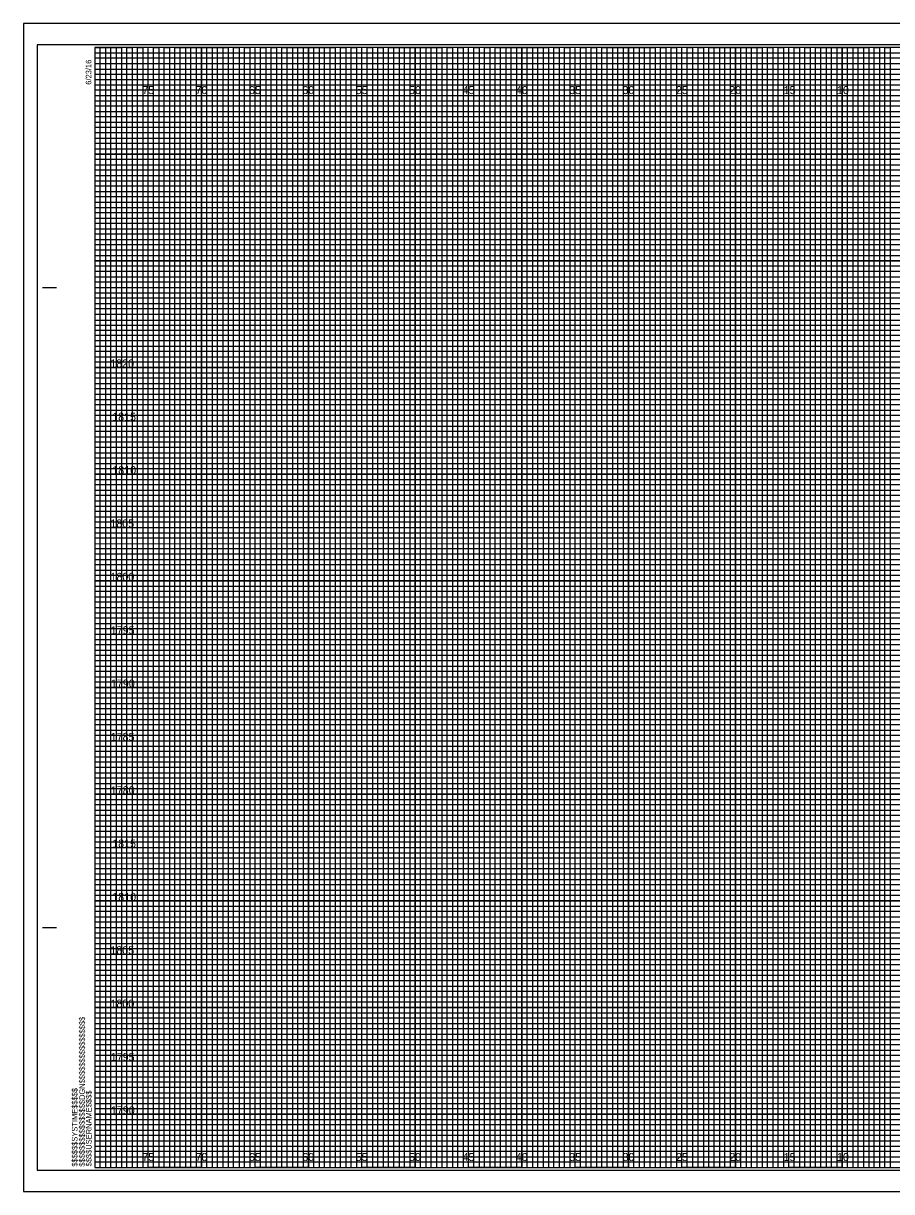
# Model space of a CAD drawing. Extents: x -7 to 162, y -2 to 767.
# Drawn here: x -6.7 to 74.6, y 327.7 to 437.2 of the extents above; entities that cross this region are included whole.
import ezdxf

# ---------------------------------------------------------------- set-up
doc = ezdxf.new("R2010")
doc.units = 0
for name, color, linetype in [('Prop Grid Mask', 7, 'Continuous'), ('Prop XS Elevation Labels', 7, 'Continuous'), ('Sheet Cross Section CELL', 7, 'Continuous'), ('Sheet Cross Section Grid Major CELL', 7, 'Continuous'), ('Sheet Cross Section Grid Middle CELL', 7, 'Continuous'), ('Sheet Cross Section Grid Minor 1 CELL', 7, 'Continuous'), ('Sheet Cross Section Grid Minor 2 CELL', 7, 'Continuous'), ('Sheet Cutting Line CELL', 7, 'Continuous'), ('Sheet DOT Grid CELL', 7, 'Continuous'), ('Sheet Plot Border Inside CELL', 7, 'Continuous'), ('Sheet Plot Border Outside CELL', 7, 'Continuous')]:
    doc.layers.add(name, color=color, linetype=linetype)

msp = doc.modelspace()

# ---------------------------------------------------------------- linework, layer by layer
at = {"layer": 'Sheet Cross Section CELL'}
for p, q in [((-4.9, 412.5), (-3.65, 412.5)), ((-4.85, 412.5), (-3.6, 412.5)), ((-4.9, 352.5), (-3.65, 352.5)), ((-4.85, 352.5), (-3.6, 352.5)), ((0, 330), (0, 330)), ((0, 330), (0, 330)), ((0, 330), (0, 330)), ((0, 330), (0, 330)), ((0, 330), (0, 330)), ((0, 330), (0, 330)), ((0, 330), (0, 330))]:
    msp.add_line(p, q, dxfattribs=at)
msp.add_lwpolyline([(160, 435), (0, 435), (0, 330), (160, 330)], close=True, dxfattribs=at)
at = {"layer": 'Sheet Cross Section Grid Major CELL'}
for p, q in [((5, 435), (0, 435)), ((5, 330), (5, 435)), ((15, 435), (10, 435)), ((10, 435), (10, 330)), ((15, 330), (15, 435)), ((25, 435), (20, 435)), ((20, 435), (20, 330)), ((25, 330), (25, 435)), ((35, 435), (30, 435)), ((30, 435), (30, 330)), ((35, 330), (35, 435)), ((45, 435), (40, 435)), ((40, 435), (40, 330)), ((45, 330), (45, 435)), ((55, 435), (50, 435)), ((50, 435), (50, 330)), ((55, 330), (55, 435)), ((65, 435), (60, 435)), ((60, 435), (60, 330)), ((65, 330), (65, 435)), ((75, 435), (70, 435)), ((70, 435), (70, 330)), ((10, 330), (5, 330)), ((20, 330), (15, 330)), ((30, 330), (25, 330)), ((40, 330), (35, 330)), ((50, 330), (45, 330)), ((60, 330), (55, 330)), ((70, 330), (65, 330))]:
    msp.add_line(p, q, dxfattribs=at)
for points in [[(0, 430), (160, 430), (160, 425), (0, 425)], [(0, 420), (160, 420), (160, 415), (0, 415)], [(0, 410), (160, 410), (160, 405), (0, 405)], [(0, 400), (160, 400), (160, 395), (0, 395)], [(0, 390), (160, 390), (160, 385), (0, 385)], [(0, 380), (160, 380), (160, 375), (0, 375)], [(0, 370), (160, 370), (160, 365), (0, 365)], [(0, 360), (160, 360), (160, 355), (0, 355)], [(0, 350), (160, 350), (160, 345), (0, 345)], [(0, 340), (160, 340), (160, 335), (0, 335)]]:
    msp.add_lwpolyline(points, dxfattribs=at)
at = {"layer": 'Sheet Cross Section Grid Middle CELL'}
for points in [[(0, 435), (2.5, 435), (2.5, 330), (7.5, 330), (7.5, 435), (12.5, 435), (12.5, 330), (17.5, 330), (17.5, 435), (22.5, 435), (22.5, 330), (27.5, 330), (27.5, 435), (32.5, 435), (32.5, 330), (37.5, 330), (37.5, 435), (42.5, 435), (42.5, 330), (47.5, 330), (47.5, 435), (52.5, 435), (52.5, 330), (57.5, 330), (57.5, 435), (62.5, 435), (62.5, 330), (67.5, 330), (67.5, 435), (72.5, 435), (72.5, 330), (77.5, 330)], [(0, 432.5), (137.5, 432.5)], [(0, 422.5), (160, 422.5), (160, 427.5), (0, 427.5)], [(0, 412.5), (160, 412.5), (160, 417.5), (0, 417.5)], [(0, 402.5), (160, 402.5), (160, 407.5), (0, 407.5)], [(0, 392.5), (160, 392.5), (160, 397.5), (0, 397.5)], [(0, 382.5), (160, 382.5), (160, 387.5), (0, 387.5)], [(0, 372.5), (160, 372.5), (160, 377.5), (0, 377.5)], [(0, 362.5), (160, 362.5), (160, 367.5), (0, 367.5)], [(0, 352.5), (160, 352.5), (160, 357.5), (0, 357.5)], [(0, 342.5), (160, 342.5), (160, 347.5), (0, 347.5)], [(0, 332.5), (160, 332.5), (160, 337.5), (0, 337.5)]]:
    msp.add_lwpolyline(points, dxfattribs=at)
at = {"layer": 'Sheet Cross Section Grid Minor 1 CELL'}
for p, q in [((0, 434.5), (130, 434.5)), ((130, 433.99), (0, 433.99)), ((0, 433.99), (0, 433.5)), ((0, 433.5), (130, 433.5)), ((130, 432.94), (0, 432.94)), ((0, 432.94), (0, 432)), ((0, 432), (160, 432))]:
    msp.add_line(p, q, dxfattribs=at)
for points in [[(0, 431.5), (135, 431.5), (160, 431.5), (160, 431), (0, 431)], [(0, 430.5), (160, 430.5), (160, 429.5), (0, 429.5)], [(0, 429), (160, 429), (160, 428.5), (0, 428.49)], [(0, 428), (160, 428), (160, 427), (0, 427)], [(0, 426.5), (160, 426.5), (160, 426), (0, 426)], [(0, 425.5), (160, 425.5), (160, 424.5), (0, 424.5)], [(0, 424), (160, 424), (160, 423.5), (0, 423.5)], [(0, 423), (160, 423), (160, 422), (0, 422)], [(0, 421.5), (160, 421.5), (160, 421), (0, 421)], [(0, 420.5), (160, 420.5), (160, 419.5), (0, 419.5)], [(0, 419), (160, 419), (160, 418.5), (0, 418.5)], [(0, 418), (160, 418), (160, 416.98), (160, 416.5), (160, 416), (0, 416)], [(0, 417), (160, 417), (160, 416.5), (0, 416.5)], [(0, 415.5), (160, 415.5), (160, 414.5), (0, 414.51)], [(0, 414.51), (160, 414.5), (160, 414), (0, 414)], [(0, 413.5), (160, 413.5), (160, 413), (0, 413)], [(0, 412), (160, 412), (160, 411.5), (0, 411.5)], [(0, 411), (160, 411), (160, 410.5), (0, 410.5)], [(-0.04, 409.44), (160, 409.44), (160, 408.94), (-0.04, 408.94)], [(0, 408.5), (160, 408.5), (160, 408), (0, 408)], [(0, 407), (160, 407), (160, 406.5), (0, 406.5)], [(0, 406), (160, 406), (160, 405.5), (0, 405.5)], [(0, 404.5), (160, 404.5), (160, 404), (0, 404)], [(0, 403.5), (160, 403.5), (160, 403), (0, 403)], [(0, 402), (160, 402), (160, 401.5), (0, 401.5)], [(0, 401), (160, 401), (160, 400.5), (0, 400.5)], [(0, 399.5), (160, 399.5), (160, 398.99), (0, 399)], [(0, 398.5), (160, 398.5), (160, 398), (0, 398)], [(0, 397), (160, 397), (160, 396.5), (0, 396.5)], [(0, 396), (160, 396), (160, 395.5), (0, 395.5)], [(0, 394.5), (160, 394.5), (160, 394), (0, 394)], [(0, 393.5), (160, 393.5), (160, 393), (0, 393)], [(0, 392), (160, 392), (160, 391.5), (0, 391.5)], [(0, 391), (160, 391), (160, 390.5), (0, 390.5)], [(0, 389.5), (160, 389.5), (160, 389), (0, 389)], [(0, 388.5), (160.03, 388.45), (160, 388), (0, 388)], [(0, 387), (160, 387), (160, 386.5), (0, 386.5)], [(0, 386), (160, 386), (160, 385.5), (0, 385.5)], [(0, 384.5), (160, 384.5), (160, 384), (0, 384)], [(0, 383.5), (160, 383.5), (160, 383), (0, 383)], [(0, 382), (160, 382), (160, 381.5), (0, 381.5)], [(0, 381), (160, 381), (160, 380.5), (0, 380.5)], [(0, 379.5), (160, 379.5), (160, 379), (0, 379)], [(0, 378.5), (160, 378.5), (160, 378), (0, 378)], [(0, 377), (160, 377), (160, 376.5), (0, 376.5)], [(0, 376), (160, 376), (160, 375.5), (0, 375.5)], [(0, 374.5), (160, 374.5), (160, 374), (0, 374)], [(0, 373.5), (160, 373.5), (160, 373), (0, 373)], [(0, 372), (160, 372), (160, 371.5), (0, 371.5)], [(0, 371), (160, 371), (160, 370.5), (0, 370.5)], [(0, 369.5), (160, 369.5), (160, 368.99), (0, 369)], [(0, 368.5), (160, 368.5), (160, 368), (0, 368)], [(0, 367), (160, 367), (160, 366.5), (0, 366.5)], [(0, 366), (160, 366), (160, 365.5), (0, 365.5)], [(0, 364.5), (160, 364.5), (160, 364), (0, 364)], [(0, 363.5), (160, 363.5), (160, 363), (0, 363)], [(0, 362), (160, 362), (160, 361.5), (0, 361.5)], [(0, 361), (160, 361), (160, 360.5), (0, 360.5)], [(0, 359.5), (160, 359.5), (160, 359), (0, 359)], [(0, 358.5), (160.03, 358.45), (160, 358), (0, 358)], [(0, 357), (160, 357), (160, 356.5), (0, 356.5)], [(0, 356), (160, 356), (160, 355.5), (0, 355.5)], [(0, 354.5), (160, 354.5), (160, 354), (0, 354)], [(0, 353.5), (160, 353.5), (160, 353), (0, 353)], [(0, 352), (160, 352), (160, 351.5), (0, 351.5)], [(0, 351), (160, 351), (160, 350.5), (0, 350.5)], [(0, 349.5), (160, 349.5), (160, 349), (0, 349)], [(0, 348.5), (160, 348.5), (160, 348), (0, 348)], [(0, 347), (160, 347), (160, 346.5), (0, 346.5)], [(0, 346), (160, 346), (160, 345.5), (0, 345.5)], [(0, 344.5), (160, 344.5), (160, 344), (0, 344)], [(0, 343.5), (160, 343.5), (160, 343), (0, 343)], [(0, 342), (160, 342), (160, 341.5), (0, 341.5)], [(0, 341), (160, 341), (160, 340.5), (0, 340.5)], [(0, 339.5), (160, 339.5), (160, 339), (0, 339)], [(0, 338.5), (160, 338.5), (160, 338), (0, 338)], [(0, 337), (160, 337), (160, 336.5), (0, 336.5)], [(0, 336), (160, 336), (160, 335.5), (0, 335.5)], [(0, 334.5), (160, 334.5), (160, 334), (0, 334)], [(0, 333.5), (160, 333.5), (160, 333), (0, 333)], [(0, 332), (160, 332), (160, 331.5), (0, 331.5)], [(0, 331), (160, 331), (160, 330.5), (0, 330.5)]]:
    msp.add_lwpolyline(points, dxfattribs=at)
at = {"layer": 'Sheet Cross Section Grid Minor 2 CELL'}
for points in [[(0, 330), (0.5, 330), (0.5, 435), (1, 435), (1, 330)], [(1, 330), (1.5, 330), (1.5, 435), (2, 435), (2, 330)], [(2.5, 330), (3, 330), (3, 435), (3.5, 435), (3.5, 330)], [(3.5, 330), (4, 330), (4, 435), (4.5, 435), (4.5, 330)], [(5, 330), (5.5, 330), (5.5, 435), (6, 435), (6, 330)], [(6, 330), (6.5, 330), (6.5, 435), (7, 435), (7, 330)], [(7.5, 330), (8, 330), (8, 435), (8.5, 435), (8.5, 330)], [(8.5, 330), (9, 330), (9, 435), (9.5, 435), (9.5, 330)], [(10, 330), (10.5, 330), (10.5, 435), (11, 435), (11, 330)], [(11, 330), (11.5, 330), (11.5, 435), (12, 435), (12, 330)], [(12.5, 330), (13, 330), (13, 435), (13.5, 435), (13.5, 330)], [(13.5, 330), (14, 330), (14, 435), (14.5, 435), (14.5, 330)], [(15, 330), (15.5, 330), (15.5, 435), (16, 435), (16, 330)], [(16, 330), (16.5, 330), (16.5, 435), (17, 435), (17, 330)], [(17.5, 330), (18, 330), (18, 435), (18.5, 435), (18.5, 330)], [(18.5, 330), (19, 330), (19, 435), (19.5, 435), (19.5, 330)], [(20, 330), (20.5, 330), (20.5, 435), (21, 435), (21, 330)], [(21, 330), (21.5, 330), (21.5, 435), (22, 435), (22, 330)], [(22.5, 330), (23, 330), (23, 435), (23.5, 435), (23.5, 330)], [(23.5, 330), (24, 330), (24, 435), (24.5, 435), (24.5, 330)], [(25, 330), (25.5, 330), (25.5, 435), (26, 435), (26, 330)], [(26, 330), (26.5, 330), (26.5, 435), (27, 435), (27, 330)], [(27.5, 330), (28, 330), (28, 435), (28.5, 435), (28.5, 330)], [(28.5, 330), (29, 330), (29, 435), (29.5, 435), (29.5, 330)], [(30, 330), (30.5, 330), (30.5, 435), (31, 435), (31, 330)], [(31, 330), (31.5, 330), (31.5, 435), (32, 435), (32, 330)], [(32.5, 330), (33, 330), (33, 435), (33.5, 435), (33.5, 330)], [(33.5, 330), (34, 330), (34, 435), (34.5, 435), (34.5, 330)], [(35, 330), (35.5, 330), (35.5, 435), (36, 435), (36, 330)], [(36, 330), (36.5, 330), (36.5, 435), (37, 435), (37, 330)], [(37.5, 330), (38, 330), (38, 435), (38.5, 435), (38.5, 330)], [(38.5, 330), (39, 330), (39, 435), (39.5, 435), (39.5, 330)], [(40, 330), (40.5, 330), (40.5, 435), (41, 435), (41, 330)], [(41, 330), (41.5, 330), (41.5, 435), (42, 435), (42, 330)], [(42.5, 330), (43, 330), (43, 435), (43.5, 435), (43.5, 330)], [(43.5, 330), (44, 330), (44, 435), (44.5, 435), (44.5, 330)], [(45, 330), (45.5, 330), (45.5, 435), (46, 435), (46, 330)], [(46, 330), (46.5, 330), (46.5, 435), (47, 435), (47, 330)], [(47.5, 330), (48, 330), (48, 435), (48.5, 435), (48.5, 330)], [(48.5, 330), (49, 330), (49, 435), (49.5, 435), (49.5, 330)], [(50, 330), (50.5, 330), (50.5, 435), (51, 435), (51, 330)], [(51, 330), (51.5, 330), (51.5, 435), (52, 435), (52, 330)], [(52.5, 330), (53, 330), (53, 435), (53.5, 435), (53.5, 330)], [(53.5, 330), (54, 330), (54, 435), (54.5, 435), (54.5, 330)], [(55, 330), (55.5, 330), (55.5, 435), (56, 435), (56, 330)], [(56, 330), (56.5, 330), (56.5, 435), (57, 435), (57, 330)], [(57.5, 330), (58, 330), (58, 435), (58.5, 435), (58.5, 330)], [(58.5, 330), (59, 330), (59, 435), (59.5, 435), (59.5, 330)], [(60, 330), (60.5, 330), (60.5, 435), (61, 435), (61, 330)], [(61, 330), (61.5, 330), (61.5, 435), (62, 435), (62, 330)], [(62.5, 330), (63, 330), (63, 435), (63.5, 435), (63.5, 330)], [(63.5, 330), (64, 330), (64, 435), (64.5, 435), (64.5, 330)], [(65, 330), (65.5, 330), (65.5, 435), (66, 435), (66, 330)], [(66, 330), (66.5, 330), (66.5, 435), (67, 435), (67, 330)], [(67.5, 330), (68, 330), (68, 435), (68.5, 435), (68.5, 330)], [(68.5, 330), (69, 330), (69, 435), (69.5, 435), (69.5, 330)], [(70, 330), (70.5, 330), (70.5, 435), (71, 435), (71, 330)], [(71, 330), (71.5, 330), (71.5, 435), (72, 435), (72, 330)], [(72.5, 330), (73, 330), (73, 435), (73.5, 435), (73.5, 330)], [(73.5, 330), (74, 330), (74, 435), (74.5, 435), (74.5, 330)]]:
    msp.add_lwpolyline(points, dxfattribs=at)
at = {"layer": 'Sheet Cutting Line CELL'}
for p, q in [((161.65, 437.25), (-6.7, 437.25)), ((-6.7, 437.25), (-6.7, 327.75)), ((-6.7, 327.75), (161.65, 327.75))]:
    msp.add_line(p, q, dxfattribs=at)
at = {"layer": 'Sheet DOT Grid CELL'}
for p, q in [((5, 330), (5, 435)), ((10, 330), (10, 435)), ((15, 330), (15, 435)), ((20, 330), (20, 435)), ((25, 330), (25, 435)), ((30, 330), (30, 435)), ((35, 330), (35, 435)), ((40, 330), (40, 435)), ((45, 330), (45, 435)), ((50, 330), (50, 435)), ((55, 330), (55, 435)), ((60, 330), (60, 435)), ((65, 330), (65, 435)), ((70, 330), (70, 435)), ((0, 430), (160, 430)), ((0, 425), (160, 425)), ((0, 420), (160, 420)), ((0, 415), (160, 415)), ((0, 410), (160, 410)), ((0, 405), (160, 405)), ((0, 400), (160, 400)), ((0, 395), (160, 395)), ((0, 390), (160, 390)), ((0, 385), (160, 385)), ((0, 380), (160, 380)), ((0, 375), (160, 375)), ((0, 370), (160, 370)), ((0, 365), (160, 365)), ((0, 360), (160, 360)), ((0, 355), (160, 355)), ((0, 350), (160, 350)), ((0, 345), (160, 345)), ((0, 340), (160, 340)), ((0, 335), (160, 335))]:
    msp.add_line(p, q, dxfattribs=at)
at = {"layer": 'Sheet Plot Border Inside CELL'}
msp.add_lwpolyline([(-5.4, 329.75), (161.2, 329.75), (161.2, 435.25), (-5.4, 435.25)], close=True, dxfattribs=at)
at = {"layer": 'Sheet Plot Border Outside CELL'}
msp.add_lwpolyline([(-6.7, 327.75), (161.65, 327.75), (161.65, 437.25), (-6.7, 437.25)], close=True, dxfattribs=at)

# ---------------------------------------------------------------- texts
at = {"layer": 'Prop Grid Mask'}
for s, p in [('75', (4.44, 430.62)), ('70', (9.43, 430.62)), ('65', (14.44, 430.62)), ('60', (19.43, 430.62)), ('55', (24.44, 430.62)), ('50', (29.43, 430.62)), ('45', (34.44, 430.62)), ('40', (39.43, 430.62)), ('35', (44.44, 430.62)), ('30', (49.43, 430.62)), ('25', (54.44, 430.62)), ('20', (59.43, 430.62)), ('15', (64.53, 430.62)), ('10', (69.52, 430.62)), ('75', (4.44, 330.62)), ('70', (9.43, 330.62)), ('65', (14.44, 330.62)), ('60', (19.43, 330.62)), ('55', (24.44, 330.62)), ('50', (29.43, 330.62)), ('45', (34.44, 330.62)), ('40', (39.43, 330.62)), ('35', (44.44, 330.62)), ('30', (49.43, 330.62)), ('25', (54.44, 330.62)), ('20', (59.43, 330.62)), ('15', (64.53, 330.62)), ('10', (69.52, 330.62))]:
    msp.add_text(s, height=0.75, dxfattribs=at).set_placement(p)
at = {"layer": 'Prop XS Elevation Labels'}
for s, p in [('1820', (1.44, 405)), ('1815', (1.62, 400)), ('1810', (1.63, 395)), ('1805', (1.45, 390)), ('1800', (1.46, 385)), ('1795', (1.49, 380)), ('1790', (1.5, 375)), ('1785', (1.48, 370)), ('1780', (1.49, 365)), ('1815', (1.62, 360)), ('1810', (1.63, 355)), ('1805', (1.45, 350)), ('1800', (1.46, 345)), ('1795', (1.49, 340)), ('1790', (1.5, 335))]:
    msp.add_text(s, height=0.75, dxfattribs=at).set_placement(p)
at = {"layer": 'Sheet Cross Section CELL'}
for s, p in [('6/23/16', (-0.33, 431.5)), ('$$$$$$$$$$$$$$$$DGN$$$$$$$$$$$$$$$$', (-0.94, 330.09)), ('$$$$$$SYSTIME$$$$$', (-1.63, 330.09)), ('$$$$USERNAME$$$$', (-0.31, 330.12))]:
    msp.add_text(s, height=0.525, rotation=90, dxfattribs=at).set_placement(p)

doc.saveas('drawing.dxf')
